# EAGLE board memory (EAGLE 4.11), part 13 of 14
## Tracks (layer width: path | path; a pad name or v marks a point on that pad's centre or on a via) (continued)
SY  (via drill 0.61) (continued)
  Bottom 0.254: 215.9,363.22 217.17,363.22 218.44,364.49 220.34,364.49 A23.S2 | 215.9,363.22 214,363.22 213.36,363.86 210.82,363.86 210.19,363.22 205.74,363.22 205.1,362.59 A24.T2 | v215.9,365.12 215.9,363.22 | v210.82,290.2 210.19,290.83 201.29,290.83 200.66,290.2 196.22,290.2 195.58,289.56 B25.U2
T0  (via drill 0.61)
  Top 0.254: v136.53,386.08 v136.53,371.48 | A33.E2 93.98,397.51 98.42,397.51 114.3,413.39 139.7,413.39 139.7,398.78 140.97,397.51 140.97,396.24 142.88,394.34 142.88,389.89 141.6,388.62 141.6,387.99 A29.J2
  Bottom 0.254: v136.53,371.48 132.08,371.48 A30.P2 | v136.53,386.08 137.16,386.72 140.97,386.72 A29.J2
T1  (via drill 0.61)
  Top 0.254: v139.7,363.22 139.7,397.51 135.25,401.96 132.08,401.96 132.08,397.51 A30.E2
  Bottom 0.254: A33.H2 93.98,391.16 94.61,391.8 99.06,391.8 102.87,395.61 107.95,395.61 108.58,396.24 111.12,396.24 112.39,394.97 120.02,394.97 121.28,396.24 123.83,396.24 125.09,394.97 128.27,394.97 129.54,396.24 131.44,396.24 A30.E2 | v139.7,363.22 137.79,363.22 137.16,363.86 130.18,363.86 128.91,362.59 A30.T2
T2  (via drill 0.61)
  Top 0.254: v95.25,377.19 95.25,382.27 93.98,383.54 A33.K2
  Route3 0.254: A30.J2 128.27,386.72 127,385.45 127,381.64 119.38,374.02 119.38,372.11 A31.P2
  Bottom 0.254: v95.25,377.19 95.89,376.56 99.06,376.56 102.87,372.75 111.76,372.75 112.39,373.38 115.57,373.38 116.84,372.11 118.75,372.11 A31.P2
T3
  Top 0.254: A31.T2 115.57,362.59 114.3,363.86 114.3,389.89 118.75,394.34 118.75,396.24 A31.E2
  Route3 0.254: A33.M2 93.98,378.46 98.42,378.46 116.2,396.24 118.75,396.24 A31.E2
T4  (via drill 0.61)
  Top 0.254: v56.52,59.05 63.5,66.04 63.5,91.44 69.85,97.79 69.85,207.01 | 69.85,207.01 69.85,305.44 73.03,308.61 v73.03,349.89 | v319.4,223.52 317.5,221.61 v317.5,214 | v71.75,207.01 69.85,207.01
  Route3 0.254: v73.03,349.89 76.2,353.06 76.2,358.14 88.9,370.84 93.34,370.84 A33.P2 | v149.86,211.45 147.96,209.55 v147.96,207.01 | A31.J2 115.57,386.72 114.3,385.45 114.3,381.64 106.68,374.02 106.68,372.11 A32.P2
  Bottom 0.254: v56.52,59.05 53.98,59.05 52.7,57.79 F36.D2 | A32.P2 106.05,372.11 101.6,372.11 100.33,373.38 97.79,373.38 96.52,372.11 93.98,372.11 A33.P2 | v319.4,223.52 325.75,223.52 327.66,225.42 331.47,225.42 C14.T2 | v317.5,214 213.36,214 212.09,215.26 173.35,215.26 172.72,214.63 153.03,214.63 v149.86,211.45 | v147.96,207.01 102.23,207.01 101.6,206.38 72.39,206.38 v71.75,207.01
T5  (via drill 0.61)
  Top 0.254: v180.97,355.6 180.97,366.4 179.71,367.67 A26.R2 | 111.12,351.16 106.68,351.16 106.68,356.24 103.5,359.41 103.5,361.31 A32.T2 | v119.38,351.16 111.12,351.16 | 111.12,351.16 111.12,382.91 104.78,389.25 104.78,394.97 106.05,396.24 A32.E2
  Route2 0.254: v140.34,352.43 139.06,351.16 v119.38,351.16
  Bottom 0.254: A33.S2 93.98,364.49 94.61,363.86 99.06,363.86 100.33,362.59 102.87,362.59 A32.T2 | v180.97,355.6 180.97,352.43 166.37,352.43 165.74,351.79 140.97,351.79 v140.34,352.43
T6  (via drill 0.61)
  Top 0.254: v96.52,358.78 98.42,360.68 98.42,373.38 100.97,375.92 100.97,376.56 101.6,377.19 101.6,385.45 102.87,386.72 A32.J2 | v334.01,212.72 334.01,220.98 334.64,221.61 C14.U2 | v212.72,213.36 212.72,285.12 215.9,288.29 215.9,323.22 212.72,326.39 212.72,375.29 v211.46,376.56 | v176.53,393.7 177.8,392.43 v177.8,378.46
  Route2 0.254: v96.52,358.78 93.98,358.78 A33.U2
  Route3 0.254: A29.L2 141.6,381.64 144.15,381.64 161.29,398.78 169.54,398.78 169.54,397.51 A27.E2
  Bottom 0.254: A29.L2 140.97,380.37 140.34,379.73 135.89,379.73 135.25,379.1 126.36,379.1 125.73,379.73 123.19,379.73 122.56,379.1 113.67,379.1 113.03,379.73 110.49,379.73 109.86,379.1 102.87,379.1 101.6,380.37 101.6,386.72 102.87,386.72 A32.J2 | v334.01,212.72 317.5,212.72 316.87,213.36 v212.72,213.36 | v211.46,376.56 210.82,377.19 208.28,377.19 A24.M2 207.65,378.46 205.74,378.46 204.47,379.73 201.29,379.73 197.49,375.92 188.59,375.92 187.32,377.19 182.88,377.19 A26.M2 182.25,378.46 v177.8,378.46 | v176.53,393.7 174.62,395.61 170.81,395.61 170.18,396.24 A27.E2
TAD  (via drill 0.61)
  Top 0.254: v254,67.31 254,52.7 255.27,51.44 F20.F2 | v254,177.16 254,233.68 255.27,234.95 v255.27,236.22 | v254,275.59 v254,250.19 | v438.15,414.02 438.15,386.08 436.88,384.81 A06.K2 | v330.2,414.66 330.2,363.86 v328.3,361.95
  Route3 0.254: v254,67.31 257.18,67.31 257.18,113.66 260.35,116.84 260.35,148.59 254,154.94 v254,177.16 | v255.27,236.22 254,237.49 v254,250.19 | v305.44,274.32 307.98,276.86 307.98,307.34 306.7,308.61 306.7,309.25 311.15,313.69 311.15,337.82 323.21,349.89 323.21,357.5 322.58,358.14 A15.U2
  Bottom 0.254: v254,275.59 255.27,276.86 269.88,276.86 271.14,275.59 302.89,275.59 304.17,274.32 v305.44,274.32 | v438.15,414.02 400.05,414.02 399.42,414.66 366.39,414.66 365.76,414.02 365.12,414.66 v330.2,414.66 | v328.3,361.95 326.39,363.86 323.85,363.86 320.68,360.68 318.13,360.68 317.5,361.31 316.23,361.31 314.32,359.41 314.32,356.87 320.68,356.87 321.94,358.14 A15.U2
TAD+IAC+CMA  (via drill 0.61)
  Top 0.254: v205.1,294 205.1,297.81 B24.R2 | v387.99,71.75 389.25,73.02 389.25,80.64 390.52,81.91 390.52,89.53 389.25,90.8 v388.62,90.8
  Route2 0.254: v205.1,294 206.38,292.74 206.38,289.56 v204.47,289.56 | v179.71,103.5 192.41,90.8 200.66,90.8 204.47,86.99 210.82,86.99 214,83.82 220.34,83.82 224.16,80.01 243.84,80.01 244.47,80.64 249.56,80.64 252.73,77.47 271.14,77.47 283.21,65.41 289.56,65.41 292.74,62.23 296.55,62.23 304.17,69.85 341,69.85 341.63,69.22 385.44,69.22 v387.99,71.75
  Route3 0.254: v204.47,289.56 193.68,278.77 193.68,224.16 187.32,217.81 187.32,178.44 184.15,175.26 184.15,172.72 v185.42,171.45 | v179.07,163.83 177.8,162.56 177.8,154.94 179.07,153.67 179.07,151.13 177.8,149.86 177.8,105.41 v179.71,103.5
  Bottom 0.254: E10.T2 382.9,89.53 384.81,91.44 385.44,91.44 E10.S2 386.08,91.44 387.99,91.44 v388.62,90.8 | v185.42,171.45 187.32,169.54 187.32,163.83 v179.07,163.83
VCC  (via drill 0.61)
  Top 0.635: v150.5,71.12 149.22,72.39 149.22,133.99 147.96,135.25 147.96,142.24 145.41,142.24 144.78,141.6 144.78,137.16 E29.A2 | 172.72,358.78 174.62,360.68 174.62,398.78 182.25,406.4 182.25,408.94 A26.A2 | 172.72,358.78 169.54,355.6 169.54,340.36 B27.A2 | 174.62,273.69 v174.62,205.1 | 174.62,273.69 176.53,275.59 182.25,275.59 182.25,273.69 C26.A2 | 172.72,358.78 174.62,356.87 174.62,273.69 | v111.12,199.39 v111.12,140.34
  Bottom 0.635: E36.A2 55.88,137.16 57.15,138.43 63.5,138.43 64.77,137.16 67.94,137.16 E35.A2 68.58,137.16 69.85,138.43 79.38,138.43 | 79.38,138.43 80.64,137.16 E34.A2 | 79.38,138.43 92.08,138.43 93.34,137.16 E33.A2 93.98,137.16 97.16,140.34 v111.12,140.34 140.97,140.34 144.15,137.16 E29.A2 144.78,137.16 146.05,138.43 155.57,138.43 156.84,137.16 E28.A2 157.48,135.89 160.02,135.89 161.29,134.62 163.83,134.62 164.47,135.25 168.91,135.25 169.54,135.89 E27.A2 170.18,135.89 172.72,135.89 173.99,134.62 176.53,134.62 177.16,135.25 181.61,135.25 182.25,135.89 E26.A2 182.88,135.89 185.42,135.89 186.69,134.62 189.23,134.62 189.87,135.25 194.31,135.25 194.94,135.89 E25.A2 195.58,135.89 198.12,135.89 199.39,134.62 201.93,134.62 202.56,135.25 207.01,135.25 207.65,135.89 E24.A2 208.28,135.89 210.82,135.89 212.09,134.62 214.63,134.62 215.26,135.25 219.71,135.25 220.34,135.89 E23.A2 220.98,135.89 221.62,135.25 226.06,135.25 226.69,134.62 227.97,134.62 229.87,136.53 233.04,136.53 E22.A2 233.68,135.89 234.31,135.25 238.76,135.25 239.4,134.62 241.3,134.62 242.57,135.89 245.75,135.89 E21.A2 246.38,135.89 247.01,135.25 251.46,135.25 252.09,134.62 254,134.62 255.27,135.89 258.44,135.89 E20.A2 259.08,135.89 259.71,135.25 264.16,135.25 264.8,134.62 266.7,134.62 267.97,135.89 271.14,135.89 E19.A2 271.78,135.89 274.32,135.89 275.59,134.62 278.13,134.62 280.04,136.53 283.85,136.53 E18.A2 284.48,135.89 285.12,135.25 289.56,135.25 290.19,134.62 292.1,134.62 293.37,135.89 296.55,135.89 E17.A2 297.18,135.89 299.72,135.89 300.99,134.62 303.53,134.62 305.44,136.53 309.25,136.53 E16.A2 309.88,136.53 313.69,136.53 315.6,134.62 316.23,134.62 316.87,135.25 321.31,135.25 321.94,135.89 E15.A2 322.58,137.16 323.21,137.79 327.66,137.79 328.3,138.43 331.47,138.43 333.38,136.53 334.64,136.53 E14.A2 335.28,135.89 337.82,135.89 339.09,134.62 341.63,134.62 342.26,135.25 346.71,135.25 347.35,135.89 E13.A2 347.98,135.89 350.52,135.89 351.79,134.62 354.33,134.62 354.96,135.25 359.41,135.25 360.05,135.89 E12.A2 360.68,136.53 363.86,136.53 365.76,134.62 367.03,134.62 368.94,136.53 372.75,136.53 E11.A2 373.38,136.53 377.19,136.53 379.1,134.62 379.73,134.62 381.63,136.53 385.44,136.53 E10.A2 386.08,135.89 390.52,135.89 391.8,134.62 393.7,134.62 394.97,135.89 398.14,135.89 E09.A2 398.78,136.53 402.59,136.53 404.5,134.62 406.4,134.62 407.67,135.89 410.85,135.89 E08.A2 411.48,135.89 412.12,135.25 416.56,135.25 417.19,134.62 419.1,134.62 420.37,135.89 423.55,135.89 E07.A2 424.18,135.89 426.72,135.89 427.99,134.62 430.53,134.62 431.17,135.25 435.61,135.25 436.25,135.89 E06.A2 436.88,135.89 439.42,135.89 440.69,134.62 443.23,134.62 443.87,135.25 448.31,135.25 448.94,135.89 E05.A2 449.58,135.89 452.12,135.89 453.39,134.62 455.93,134.62 456.56,135.25 461.01,135.25 461.64,135.89 E04.A2 462.28,135.89 464.82,135.89 466.09,134.62 468.63,134.62 470.54,136.53 474.35,136.53 E03.A2
  Bottom 0.635: F03.A2 474.35,66.04 473.71,65.41 469.26,65.41 468.63,64.77 466.09,64.77 464.82,66.04 462.28,66.04 F04.A2 461.64,67.31 460.38,68.58 450.85,68.58 449.58,67.31 F05.A2 448.94,67.31 447.68,68.58 440.69,68.58 439.42,67.31 436.88,67.31 F06.A2 436.25,67.31 434.98,68.58 422.27,68.58 | 412.75,68.58 411.48,67.31 F08.A2 | 412.75,68.58 422.27,68.58 | 422.27,68.58 423.55,67.31 F07.A2 | 412.75,68.58 404.5,68.58 402.59,66.67 398.78,66.67 F09.A2 398.14,66.04 394.97,66.04 393.7,64.77 391.8,64.77 391.16,65.41 386.71,65.41 386.08,66.04 F10.A2 385.44,66.67 381.63,66.67 379.73,64.77 377.19,64.77 375.92,66.04 373.38,66.04 F11.A2 372.75,67.31 368.3,67.31 367.03,68.58 358.77,68.58 | 15.88,68.58 6.35,68.58 5.08,67.31 F40.A2 | 15.88,68.58 17.14,67.31 F39.A2 | 28.57,68.58 29.84,67.31 F38.A2 | 28.57,68.58 15.88,68.58 | 41.27,68.58 42.55,67.31 F37.A2 | 41.27,68.58 28.57,68.58 | 53.98,68.58 55.24,67.31 F36.A2 | 53.98,68.58 41.27,68.58 | 66.67,68.58 67.94,67.31 F35.A2 | 66.67,68.58 53.98,68.58 | 79.38,68.58 80.64,67.31 F34.A2 | 79.38,68.58 66.67,68.58 | 89.53,67.94 88.27,67.94 87.63,68.58 79.38,68.58 | 89.53,67.94 92.71,67.94 93.34,67.31 F33.A2 | 168.28,68.58 158.75,68.58 157.48,67.31 F28.A2 156.84,67.31 153.67,70.48 150.5,70.48 | 168.28,68.58 169.54,67.31 F27.A2 | 168.28,68.58 180.97,68.58 182.25,67.31 F26.A2 182.88,66.04 185.42,66.04 186.69,64.77 189.23,64.77 189.87,65.41 194.31,65.41 194.94,66.04 F25.A2 195.58,66.04 198.12,66.04 199.39,64.77 201.93,64.77 202.56,65.41 207.01,65.41 207.65,66.04 F24.A2 208.28,66.67 212.09,66.67 214,64.77 214.63,64.77 215.26,65.41 219.71,65.41 220.34,66.04 F23.A2 220.98,66.04 221.62,65.41 226.06,65.41 226.69,64.77 227.33,64.77 229.24,66.67 233.04,66.67 F22.A2 233.68,66.04 234.31,65.41 238.76,65.41 239.4,64.77 241.3,64.77 242.57,66.04 245.75,66.04 F21.A2 246.38,66.04 248.92,66.04 250.19,64.77 252.73,64.77 253.37,65.41 257.81,65.41 258.44,66.04 F20.A2 259.08,66.04 261.62,66.04 262.89,64.77 265.43,64.77 266.06,65.41 270.51,65.41 271.14,66.04 F19.A2 271.78,67.31 273.05,68.58 282.57,68.58 283.85,67.31 F18.A2 284.48,66.04 287.02,66.04 288.29,64.77 290.83,64.77 292.74,66.67 296.55,66.67 F17.A2 297.18,67.31 297.81,67.94 302.26,67.94 302.89,68.58 307.98,68.58
  Bottom 0.635: 346.07,68.58 336.55,68.58 335.28,67.31 F14.A2 334.64,66.67 330.83,66.67 328.93,64.77 326.39,64.77 325.12,66.04 322.58,66.04 F15.A2 321.94,67.31 317.5,67.31 316.23,68.58 307.98,68.58 | 346.07,68.58 347.35,67.31 F13.A2 | 358.77,68.58 360.05,67.31 F12.A2 | 346.07,68.58 358.77,68.58 | 307.98,68.58 309.25,67.31 F16.A2 | 89.53,67.94 89.53,70.48 150.5,70.48 | v150.5,71.12 150.5,70.48 | B03.A2 474.35,339.09 473.71,338.46 469.26,338.46 468.63,337.82 466.09,337.82 464.82,339.09 462.28,339.09 B04.A2 461.64,339.09 461.01,338.46 456.56,338.46 455.93,337.82 453.39,337.82 452.12,339.09 449.58,339.09 B05.A2 448.94,339.09 448.31,338.46 443.87,338.46 443.23,337.82 440.69,337.82 439.42,339.09 436.88,339.09 B06.A2 436.25,339.09 433.07,339.09 431.8,337.82 429.89,337.82 429.26,338.46 424.81,338.46 424.18,339.09 B07.A2 423.55,339.09 420.37,339.09 419.1,337.82 417.19,337.82 415.29,339.73 411.48,339.73 B08.A2 410.85,339.73 408.31,339.73 406.4,337.82 404.5,337.82 403.86,338.46 399.42,338.46 398.78,339.09 B09.A2 398.14,339.09 397.51,338.46 393.06,338.46 392.43,337.82 389.89,337.82 389.25,338.46 384.81,338.46 | 384.81,338.46 385.44,339.09 B10.A2 | 384.81,338.46 380.37,338.46 379.73,337.82 377.19,337.82 375.92,339.09 373.38,339.09 B11.A2 372.75,339.09 372.11,338.46 367.67,338.46 367.03,337.82 364.49,337.82 363.22,339.09 360.68,339.09 B12.A2 360.05,339.09 359.41,338.46 354.96,338.46 354.33,337.82 351.79,337.82 350.52,339.09 347.98,339.09 B13.A2 347.35,339.09 346.71,338.46 342.26,338.46 341.63,337.82 339.09,337.82 337.82,339.09 335.28,339.09 B14.A2 334.64,339.09 334.01,338.46 329.56,338.46 328.93,337.82 326.39,337.82 325.12,339.09 322.58,339.09 B15.A2 321.94,339.09 321.31,338.46 316.87,338.46 316.23,337.82 313.69,337.82 312.42,339.09 309.88,339.09 B16.A2 309.25,339.09 306.07,339.09 304.8,337.82 302.89,337.82 302.26,338.46 297.81,338.46 297.18,339.09 B17.A2 296.55,339.09 295.91,338.46 291.46,338.46 290.83,337.82 289.56,337.82 287.65,339.73 284.48,339.73 B18.A2 283.85,339.09 283.21,338.46 278.76,338.46 278.13,337.82 275.59,337.82 274.32,339.09 271.78,339.09 B19.A2 271.14,339.09 267.97,339.09 266.7,337.82 264.8,337.82 264.16,338.46 259.71,338.46 259.08,339.09 B20.A2 258.44,339.73 255.27,339.73 253.37,337.82 252.09,337.82 251.46,338.46 247.01,338.46 246.38,339.09 B21.A2 245.75,339.09 242.57,339.09 241.3,337.82 239.4,337.82 238.76,338.46 234.31,338.46 233.68,339.09 B22.A2 233.04,339.09 229.87,339.09 228.6,337.82 226.69,337.82 226.06,338.46 221.62,338.46 220.98,339.09 B23.A2 220.34,339.09 219.71,338.46 215.26,338.46 214.63,337.82 212.09,337.82 210.82,339.09 208.28,339.09 B24.A2 207.65,339.09 207.01,338.46 202.56,338.46 201.93,337.82 199.39,337.82 198.12,339.09 195.58,339.09 B25.A2 194.94,339.09 194.31,338.46 189.87,338.46 189.23,337.82 186.69,337.82 185.42,339.09 182.88,339.09 B26.A2 182.25,339.09 179.07,339.09 177.8,337.82 175.9,337.82 175.26,338.46 170.81,338.46 170.18,339.09 B27.A2 169.54,339.73 165.74,339.73 163.83,337.82 161.29,337.82 160.02,339.09 157.48,339.09 B28.A2 156.84,339.73 153.03,339.73 151.13,337.82 148.59,337.82 147.32,339.09 144.78,339.09 B29.A2 144.15,340.36 139.7,340.36 138.43,341.63 130.18,341.63
  Bottom 0.635: 28.57,341.63 6.35,341.63 5.08,340.36 B40.A2 | 28.57,341.63 29.84,340.36 B38.A2 | 41.27,341.63 42.55,340.36 B37.A2 | 41.27,341.63 28.57,341.63 | 53.98,341.63 55.24,340.36 B36.A2 | 53.98,341.63 41.27,341.63 | 53.98,341.63 66.67,341.63 67.94,340.36 B35.A2 68.58,340.36 69.85,341.63 76.83,341.63 78.11,340.36 80.64,340.36 B34.A2 81.28,340.36 82.55,341.63 92.08,341.63 | 92.08,341.63 93.34,340.36 B33.A2 | 104.78,341.63 106.05,340.36 B32.A2 | 104.78,341.63 92.08,341.63 | 117.47,341.63 118.75,340.36 B31.A2 | 117.47,341.63 104.78,341.63 | 130.18,341.63 131.44,340.36 B30.A2 | 130.18,341.63 117.47,341.63 | 422.27,411.48 412.75,411.48 411.48,410.21 A08.A2 410.85,408.94 410.21,408.31 405.76,408.31 405.13,407.67 402.59,407.67 401.32,408.94 398.78,408.94 A09.A2 398.14,410.21 396.88,411.48 384.18,411.48 | 422.27,411.48 423.55,410.21 A07.A2 | 422.27,411.48 434.98,411.48 436.25,410.21 A06.A2 436.88,408.94 439.42,408.94 440.69,407.67 443.23,407.67 443.87,408.31 448.31,408.31 448.94,408.94 A05.A2 449.58,408.94 452.12,408.94 453.39,407.67 455.93,407.67 456.56,408.31 461.01,408.31 461.64,408.94 A04.A2 462.28,408.94 464.82,408.94 466.09,407.67 468.63,407.67 469.26,408.31 473.71,408.31 474.35,408.94 A03.A2 | 384.18,411.48 379.1,411.48 378.46,410.85 374.01,410.85 373.38,410.21 A11.A2 372.75,408.94 372.11,408.31 367.67,408.31 367.03,407.67 364.49,407.67 363.22,408.94 360.68,408.94 A12.A2 360.05,410.21 358.77,411.48 346.07,411.48 | 384.18,411.48 385.44,410.21 A10.A2 | 346.07,411.48 336.55,411.48 335.28,410.21 A14.A2 334.64,408.94 330.2,408.94 328.93,407.67 326.39,407.67 325.12,408.94 322.58,408.94 A15.A2 321.94,410.21 318.13,410.21 316.87,411.48 311.15,411.48
  Bottom 0.635: 346.07,411.48 347.35,410.21 A13.A2 | 311.15,411.48 309.88,410.21 A16.A2 | 311.15,411.48 302.89,411.48 300.99,409.58 297.18,409.58 A17.A2 296.55,408.94 293.37,408.94 292.1,407.67 290.19,407.67 289.56,408.31 285.12,408.31 284.48,408.94 A18.A2 283.85,409.58 280.04,409.58 278.13,407.67 275.59,407.67 274.32,408.94 271.78,408.94 A19.A2 271.14,408.94 270.51,408.31 266.06,408.31 265.43,407.67 262.89,407.67 261.62,408.94 259.08,408.94 A20.A2 258.44,408.94 257.81,408.31 253.37,408.31 252.73,407.67 250.19,407.67 248.92,408.94 246.38,408.94 A21.A2 245.75,408.94 245.11,408.31 240.66,408.31 240.03,407.67 237.49,407.67 236.22,408.94 233.68,408.94 A22.A2 233.04,408.94 232.41,408.31 227.97,408.31 227.33,407.67 224.79,407.67 223.52,408.94 220.98,408.94 A23.A2 220.34,408.94 219.71,408.31 215.26,408.31 214.63,407.67 212.09,407.67 210.82,408.94 208.28,408.94 A24.A2 207.65,408.94 207.01,408.31 202.56,408.31 201.93,407.67 199.39,407.67 198.12,408.94 195.58,408.94 A25.A2 194.94,408.94 194.31,408.31 189.87,408.31 189.23,407.67 186.69,407.67 185.42,408.94 182.88,408.94 A26.A2 182.25,410.21 180.97,411.48 171.45,411.48 170.18,410.21 A27.A2 169.54,410.21 165.74,410.21 164.47,411.48 158.75,411.48 157.48,410.21 A28.A2 156.84,408.94 153.67,408.94 152.4,407.67 150.5,407.67 149.86,408.31 145.41,408.31 144.78,408.94 A29.A2 144.15,408.94 140.97,408.94 139.7,407.67 137.79,407.67 137.16,408.31 132.72,408.31 132.08,408.94 A30.A2 131.44,410.21 130.18,411.48 117.47,411.48 | 15.88,411.48 6.35,411.48 5.08,410.21 A40.A2 | 15.88,411.48 17.14,410.21 A39.A2
  Bottom 0.635: 28.57,411.48 29.84,410.21 A38.A2 | 28.57,411.48 15.88,411.48 | 41.27,411.48 42.55,410.21 A37.A2 | 41.27,411.48 28.57,411.48 | 53.98,411.48 55.24,410.21 A36.A2 | 53.98,411.48 41.27,411.48 | 66.67,411.48 67.94,410.21 A35.A2 | 66.67,411.48 53.98,411.48 | 79.38,411.48 80.64,410.21 A34.A2 | 79.38,411.48 66.67,411.48 | 92.08,411.48 93.34,410.21 A33.A2 | 92.08,411.48 79.38,411.48 | 104.78,411.48 106.05,410.21 A32.A2 | 104.78,411.48 92.08,411.48 | 117.47,411.48 118.75,410.21 A31.A2 | 117.47,411.48 104.78,411.48 | 28.57,205.1 19.05,205.1 17.78,203.84 D39.A2 | 28.57,205.1 29.84,203.84 D38.A2 | 28.57,205.1 41.27,205.1 42.55,203.84 D37.A2 43.18,202.56 45.72,202.56 46.99,201.29 49.53,201.29 50.16,201.93 54.61,201.93 55.24,202.56 D36.A2 55.88,202.56 58.42,202.56 59.69,201.29 62.23,201.29 62.87,201.93 67.31,201.93 67.94,202.56 D35.A2 68.58,202.56 71.12,202.56 72.39,201.29 74.93,201.29 75.56,201.93 80.01,201.93 80.64,202.56 D34.A2 81.28,203.2 85.09,203.2 87,201.29 88.9,201.29 90.17,202.56 93.34,202.56 D33.A2 93.98,202.56 94.61,201.93 99.06,201.93 99.69,201.29 101.6,201.29 102.87,202.56 106.05,202.56 D32.A2 106.68,202.56 109.22,202.56 110.49,201.29 111.12,201.29 | 111.12,201.29 113.03,201.29 113.67,201.93 118.11,201.93 118.75,202.56 D31.A2 119.38,202.56 121.92,202.56 123.19,201.29 125.73,201.29 126.36,201.93 130.81,201.93 131.44,202.56 D30.A2 132.08,202.56 134.62,202.56 135.89,201.29 138.43,201.29 139.06,201.93 143.51,201.93 144.15,202.56 D29.A2 144.78,202.56 145.41,201.93 149.86,201.93 150.5,201.29 152.4,201.29 153.67,202.56 156.84,202.56 D28.A2 157.48,203.84 161.93,203.84 163.19,205.1 168.28,205.1
  Bottom 0.635: 168.28,205.1 169.54,203.84 D27.A2 | 168.28,205.1 v174.62,205.1 180.97,205.1 182.25,203.84 D26.A2 182.88,202.56 185.42,202.56 186.69,201.29 189.23,201.29 190.5,202.56 194.94,202.56 D25.A2 195.58,203.84 196.85,205.1 206.38,205.1 207.65,203.84 D24.A2 208.28,202.56 208.91,201.93 213.36,201.93 214,201.29 215.9,201.29 217.81,203.2 220.34,203.2 D23.A2 220.98,203.84 222.25,205.1 231.78,205.1 | D03.A2 474.35,202.56 473.71,201.93 469.26,201.93 468.63,201.29 466.09,201.29 464.82,202.56 462.28,202.56 D04.A2 461.64,202.56 461.01,201.93 456.56,201.93 455.93,201.29 453.39,201.29 452.12,202.56 449.58,202.56 D05.A2 448.94,202.56 445.77,202.56 444.5,201.29 442.6,201.29 441.96,201.93 437.51,201.93 436.88,202.56 D06.A2 436.25,202.56 433.07,202.56 431.8,201.29 429.89,201.29 429.26,201.93 424.81,201.93 424.18,202.56 D07.A2 423.55,202.56 422.91,201.93 418.46,201.93 417.83,201.29 415.29,201.29 414.02,202.56 411.48,202.56 D08.A2 410.85,202.56 407.67,202.56 406.4,201.29 404.5,201.29 403.86,201.93 399.42,201.93 398.78,202.56 D09.A2 398.14,203.2 394.33,203.2 392.43,201.29 391.16,201.29 389.25,203.2 386.08,203.2 D10.A2 385.44,202.56 384.81,201.93 380.37,201.93 379.73,201.29 377.19,201.29 375.92,202.56 373.38,202.56 D11.A2 372.75,202.56 369.57,202.56 368.3,201.29 366.39,201.29 365.76,201.93 361.31,201.93 360.68,202.56 D12.A2 360.05,203.2 356.24,203.2 354.33,201.29 351.79,201.29 350.52,202.56 347.98,202.56 D13.A2 347.35,202.56 346.71,201.93 342.26,201.93 341.63,201.29 339.09,201.29 337.82,202.56 335.28,202.56 D14.A2 334.64,202.56 334.01,201.93 329.56,201.93 328.93,201.29 326.39,201.29 325.12,202.56 322.58,202.56 D15.A2 321.94,202.56 321.31,201.93 316.87,201.93 316.23,201.29 313.69,201.29 312.42,202.56 309.88,202.56 D16.A2 309.25,202.56 308.61,201.93 304.17,201.93 303.53,201.29 300.99,201.29 299.72,202.56 297.18,202.56 D17.A2 296.55,202.56 293.37,202.56 292.1,201.29 290.19,201.29 289.56,201.93 285.12,201.93 284.48,202.56 D18.A2 283.85,202.56 280.67,202.56 279.4,201.29 277.5,201.29 276.86,201.93 272.42,201.93 271.78,202.56 D19.A2 271.14,203.84 269.88,205.1 257.18,205.1
  Bottom 0.635: 231.78,205.1 233.04,203.84 D22.A2 | 244.47,205.1 245.75,203.84 D21.A2 | 231.78,205.1 244.47,205.1 | 257.18,205.1 258.44,203.84 D20.A2 | 244.47,205.1 257.18,205.1 | C03.A2 474.35,273.05 471.17,273.05 469.26,271.15 468,271.15 467.36,271.78 462.92,271.78 462.28,272.42 C04.A2 461.64,272.42 461.01,271.78 456.56,271.78 455.93,271.15 453.39,271.15 452.75,271.78 448.31,271.78 | 448.31,271.78 448.94,272.42 C05.A2 | 448.31,271.78 443.87,271.78 443.23,271.15 440.69,271.15 439.42,272.42 436.88,272.42 C06.A2 436.25,272.42 435.61,271.78 431.17,271.78 430.53,271.15 427.99,271.15 426.72,272.42 424.18,272.42 C07.A2 423.55,272.42 420.37,272.42 419.1,271.15 417.19,271.15 416.56,271.78 412.12,271.78 411.48,272.42 C08.A2 410.85,273.05 407.04,273.05 405.13,271.15 403.86,271.15 401.95,273.05 398.78,273.05 C09.A2 398.14,272.42 397.51,271.78 393.06,271.78 392.43,271.15 389.89,271.15 388.62,272.42 386.08,272.42 C10.A2 385.44,273.05 381.63,273.05 379.73,274.96 371.48,274.96 | 371.48,274.96 366.39,274.96 364.49,273.05 360.68,273.05 C12.A2 360.05,272.42 359.41,271.78 354.96,271.78 354.33,271.15 353.06,271.15 351.15,273.05 347.98,273.05 C13.A2 347.35,273.05 343.54,273.05 341.63,271.15 339.09,271.15 337.82,272.42 335.28,272.42 C14.A2 334.64,272.42 334.01,271.78 329.56,271.78 328.93,271.15 326.39,271.15 325.12,272.42 322.58,272.42 C15.A2 321.94,272.42 321.31,271.78 316.87,271.78 316.23,271.15 313.69,271.15 312.42,272.42 309.88,272.42 C16.A2 309.25,272.42 308.61,271.78 304.17,271.78 303.53,271.15 300.99,271.15 299.72,272.42 297.18,272.42 C17.A2 296.55,272.42 293.37,272.42 292.1,271.15 290.19,271.15 288.93,272.42 284.48,272.42 C18.A2 283.85,272.42 283.21,271.78 278.76,271.78 278.13,271.15 276.86,271.15 274.95,273.05 271.78,273.05 C19.A2 271.14,272.42 267.97,272.42 266.7,271.15 264.8,271.15 264.16,271.78 259.71,271.78 259.08,272.42 C20.A2 258.44,273.05 254.63,273.05 252.73,271.15 250.19,271.15 248.92,272.42 246.38,272.42 C21.A2 245.75,272.42 245.11,271.78 240.66,271.78 240.03,271.15 238.76,271.15 236.85,273.05 233.68,273.05 C22.A2 233.04,273.69 228.6,273.69 227.33,274.96 219.07,274.96
  Bottom 0.635: 371.48,274.96 372.75,273.69 C11.A2 | 219.07,274.96 209.55,274.96 208.28,273.69 C24.A2 207.65,273.05 203.84,273.05 201.93,271.15 199.39,271.15 198.12,272.42 195.58,272.42 C25.A2 194.94,272.42 194.31,271.78 189.87,271.78 189.23,271.15 186.69,271.15 185.42,272.42 182.88,272.42 C26.A2 182.25,273.05 178.44,273.05 176.53,274.96 168.28,274.96 | 219.07,274.96 220.34,273.69 C23.A2 | C40.A2 5.08,272.42 5.71,271.78 10.16,271.78 10.79,271.15 12.7,271.15 13.97,272.42 17.14,272.42 C39.A2 17.78,272.42 20.32,272.42 21.59,271.15 24.13,271.15 24.77,271.78 29.21,271.78 29.84,272.42 C38.A2 30.48,272.42 33.02,272.42 34.29,271.15 36.83,271.15 37.47,271.78 41.91,271.78 42.55,272.42 C37.A2 43.18,272.42 45.72,272.42 46.99,271.15 49.53,271.15 50.16,271.78 54.61,271.78 55.24,272.42 C36.A2 55.88,272.42 56.52,271.78 60.96,271.78 61.59,271.15 63.5,271.15 64.77,272.42 67.94,272.42 C35.A2 68.58,272.42 69.22,271.78 73.66,271.78 74.3,271.15 76.2,271.15 77.47,272.42 80.64,272.42 C34.A2 81.28,272.42 83.82,272.42 85.09,271.15 87.63,271.15 88.27,271.78 92.71,271.78 93.34,272.42 C33.A2 93.98,273.05 97.16,273.05 99.06,274.96 104.78,274.96 106.05,273.69 C32.A2 106.68,272.42 109.22,272.42 110.49,271.15 113.03,271.15 113.67,271.78 118.11,271.78 118.75,272.42 C31.A2 119.38,273.69 123.83,273.69 125.09,274.96 130.18,274.96 131.44,273.69 C30.A2 132.08,272.42 134.62,272.42 135.89,271.15 138.43,271.15 139.06,271.78 143.51,271.78 144.15,272.42 C29.A2 144.78,272.42 147.32,272.42 148.59,271.15 151.13,271.15 151.76,271.78 156.21,271.78 156.84,272.42 C28.A2 157.48,273.69 158.75,274.96 168.28,274.96
  Bottom 0.635: 168.28,274.96 169.54,273.69 C27.A2 | 111.12,201.29 v111.12,199.39
WR\  (via drill 0.61)
  Top 0.254: v160.66,177.16 160.02,177.8 160.02,179.07 158.75,180.34 158.75,216.53 157.48,217.81 157.48,221.61 C28.U2
  Bottom 0.254: v160.66,177.16 161.93,175.89 165.74,175.89 166.37,175.26 D27.L2
WR_RQ  (via drill 0.61)
  Top 0.254: 104.78,141.6 104.78,160.02 103.5,161.29 D32.R2 | 104.78,141.6 104.78,20.95 103.5,19.69 F32.T2 | v142.88,140.97 142.88,125.73 144.15,124.46 E29.E2 | v103.5,141.6 104.78,141.6
  Bottom 0.254: v142.88,140.97 140.97,142.88 120.02,142.88 118.75,141.6 v103.5,141.6
WRITE  (via drill 0.61)
  Top 0.254: v128.91,185.42 127,183.51 127,65.41 v125.09,63.5 | v116.2,61.59 116.2,57.79 F31.D2
  Bottom 0.254: F32.E2 106.68,54.61 107.31,55.25 111.76,55.25 113.03,56.52 115.57,56.52 F31.D2 | v128.91,185.42 135.25,185.42 135.89,186.06 140.34,186.06 140.97,186.69 D29.F2 | v125.09,63.5 123.19,61.59 v116.2,61.59
WT_INCR  (via drill 0.61)
  Top 0.254: v189.23,298.45 187.32,300.36 v187.32,346.08 | v325.12,340.36 325.75,341 325.75,353.7 327.02,354.97 v327.02,387.35 | v334.64,387.35 334.64,389.89 A14.H2
  Route2 0.254: v189.23,298.45 191.77,298.45 B25.R2 | v334.64,387.35 332.11,387.35 A14.J2
  Bottom 0.254: v187.32,346.08 215.9,346.08 216.53,346.71 222.88,346.71 224.16,345.44 241.94,345.44 242.57,346.08 247.65,346.08 250.19,343.54 264.8,343.54 265.43,344.17 297.18,344.17 298.45,345.44 300.36,345.44 303.53,342.27 316.23,342.27 318.13,340.36 320.68,340.36 321.31,341 324.49,341 v325.12,340.36 | v327.02,387.35 331.47,387.35 A14.J2
WTB  (via drill 0.61)
  Top 0.254: v385.44,167 384.18,168.28 v384.18,208.28 | v346.71,208.28 342.9,212.09 342.9,233.04 344.17,234.31 344.17,237.49 C13.N2 | v442.6,354.97 444.5,356.87 444.5,375.29 448.31,379.1 448.31,382.91 448.94,383.54 A05.K2 | v429.89,219.07 429.26,218.44 429.26,208.28 v429.89,207.64
  Route2 0.254: v401.32,157.48 400.05,158.75 400.05,163.83 397.51,163.83 391.16,170.18 388.62,170.18 v385.44,167
  Route3 0.254: v414.65,377.83 411.48,374.65 411.48,374.02 412.75,372.75 412.75,363.86 407.67,363.86 403.23,359.41 398.78,359.41 A09.U2 | v430.53,349.89 428.62,347.98 428.62,273.69 427.36,272.42 427.36,271.78 428.62,270.51 428.62,220.34 v429.89,219.07
  Bottom 0.254: v414.65,377.83 422.27,385.45 429.26,385.45 433.07,389.25 441.96,389.25 446.4,384.81 448.94,384.81 A05.K2 | v401.32,157.48 403.23,157.48 403.23,155.57 404.5,154.31 409.57,154.31 410.85,153.03 D08.U2 | v346.71,208.28 347.98,209.55 366.39,209.55 367.03,208.91 383.54,208.91 v384.18,208.28 385.44,207.01 390.52,207.01 391.8,208.28 429.26,208.28 v429.89,207.64 | v442.6,354.97 440.69,353.06 433.7,353.06 v430.53,349.89
WTB*A00(B)  (via drill 0.61)
  Top 0.254: v117.47,131.44 117.47,153.67 116.2,154.94 D31.T2
  Route2 0.254: v117.47,131.44 117.47,124.46 118.75,124.46 E31.E2
WTD  (via drill 0.61)
  Top 0.254: v447.68,374.02 447.68,367.03 448.94,365.76 A05.S2 | v337.82,117.47 339.73,119.38 339.73,231.14 342.9,234.31 342.9,259.08 344.17,260.35 344.17,262.89 C13.D2 344.17,264.16 344.17,266.7 342.9,267.97 v342.9,274.96 | v304.8,316.23 v304.8,276.23 | v309.88,399.42 307.98,397.51 v307.98,364.49 | v313.06,358.78 313.69,358.14 313.69,356.87 314.96,355.6 314.96,341 314.32,340.36 v314.32,326.39
  Route2 0.254: A08.M2 410.85,378.46 410.85,380.37 401.95,389.25 399.42,389.25 398.78,389.89 A09.H2 398.14,391.16 396.88,392.43 389.89,392.43 389.25,391.8 380.37,391.8 373.38,398.78 364.49,398.78 363.86,398.15 354.96,398.15 351.15,401.96 v343.54,401.96 | v337.82,117.47 335.28,117.47 E14.H2
  Route3 0.254: v307.98,364.49 313.06,359.41 v313.06,358.78 | v314.32,326.39 314.32,322.58 v312.42,320.68
  Bottom 0.254: v447.68,374.02 447.68,375.92 440.69,375.92 440.06,376.56 431.17,376.56 430.53,375.92 427.99,375.92 427.36,376.56 421.64,376.56 421,375.92 415.29,375.92 414.02,377.19 411.48,377.19 A08.M2 | v304.8,276.23 306.07,274.96 325.12,274.96 325.75,274.32 327.66,274.32 328.93,275.59 342.26,275.59 v342.9,274.96 | B17.J2 294,316.87 294.64,316.23 299.08,316.23 299.72,315.6 302.26,315.6 302.89,316.23 v304.8,316.23 304.8,320.04 306.7,321.95 311.15,321.95 v312.42,320.68 | v343.54,401.96 342.9,401.32 339.09,401.32 338.45,401.96 329.56,401.96 328.93,401.32 326.39,401.32 325.75,401.96 316.87,401.96 316.23,401.32 313.69,401.32 313.06,401.96 312.42,401.96 v309.88,399.42
WTD(B)  (via drill 0.61)
  Top 0.254: v111.12,73.66 111.12,139.06 113.03,140.97 v113.03,148.59
  Route2 0.254: v111.12,73.66 111.12,33.66 117.47,27.3 118.75,27.3 118.75,22.86 F31.S2 | v113.03,148.59 128.27,163.83 137.16,163.83 138.43,162.56 140.97,162.56 D29.R2
WTE  (via drill 0.61)
  Top 0.254: A10.U2 385.44,359.41 384.18,360.68 384.18,366.4 382.9,367.67 A10.R2 | 395.61,338.46 391.8,342.27 v391.8,354.97 | 403.23,330.84 395.61,338.46 | 403.23,330.84 v403.86,330.2 | v419.74,164.47 419.1,165.1 v419.1,276.23 | v404.5,279.4 403.23,280.67 403.23,330.84 | v450.85,342.9 450.85,375.92 449.58,377.19 A05.M2 | v399.42,342.9 395.61,339.09 395.61,338.46 | v179.07,278.13 180.97,280.04 180.97,290.2 179.71,291.47 B26.T2 | v76.2,277.5 76.2,379.1 77.47,380.37 A34.L2 | v319.4,300.99 317.5,299.09 v317.5,279.4 | v187.96,284.48 185.42,281.94 v185.42,278.13
  Route2 0.254: v419.74,164.47 423.55,164.47 D07.P2 | v319.4,300.99 321.94,300.99 B15.P2 | v404.5,279.4 404.5,276.23 392.43,276.23 391.16,274.96 363.86,274.96 363.22,274.32 362.58,274.32 v361.95,274.96
  Route3 0.254: v253.37,280.67 v253.37,284.48 | v332.11,274.32 331.47,274.96 v331.47,279.4
  Bottom 0.254: A15.R2 319.4,367.67 320.68,366.4 327.66,366.4 330.83,369.57 337.19,369.57 337.82,370.21 340.36,370.21 344.17,366.4 351.79,366.4 355.6,370.21 365.76,370.21 366.39,369.57 375.29,369.57 375.92,370.21 377.82,370.21 379.73,368.3 382.27,368.3 A10.R2 | v403.86,330.2 407.67,330.2 B08.D2 | v391.8,354.97 388.62,358.14 386.08,358.14 A10.U2 | v419.1,276.23 415.93,279.4 v404.5,279.4 | v450.85,342.9 450.21,342.27 400.69,342.27 400.05,342.9 v399.42,342.9 | v76.2,277.5 76.83,278.13 139.06,278.13 140.34,276.86 161.93,276.86 163.83,278.77 178.44,278.77 v179.07,278.13 v185.42,278.13 | v253.37,280.67 254,280.04 291.46,280.04 292.1,280.67 292.74,280.04 316.87,280.04 v317.5,279.4 v331.47,279.4 | v253.37,284.48 250.19,284.48 249.56,283.85 188.59,283.85 v187.96,284.48 | v361.95,274.96 361.31,274.32 354.96,274.32 354.33,274.96 344.17,274.96 342.9,273.69 341.63,274.96 332.74,274.96 v332.11,274.32
WTE*-[(ISZ*ZI)+JMS+(OP+IOT)*SKP+JMP]  (via drill 0.61)
  Top 0.254: E14.M2 335.28,105.41 335.28,109.22 336.55,110.49 336.55,217.17 335.28,218.44 335.28,220.34 336.55,221.61 336.55,236.22 335.28,237.49 335.28,240.66 C14.M2
  Route2 0.254: v389.25,254 384.81,249.56 377.19,249.56 374.01,246.38 367.67,246.38 367.03,245.75 364.49,245.75 361.31,248.92 358.77,248.92 v354.33,244.47
  Route3 0.254: v391.8,276.86 390.52,275.59 390.52,255.27 v389.25,254
  Bottom 0.254: v391.8,276.86 399.42,276.86 399.42,280.04 396.24,283.21 395.61,283.21 395.61,283.85 402.59,290.83 407.04,290.83 407.67,291.47 B08.T2 | v354.33,244.47 352.43,242.57 342.26,242.57 341.63,243.2 339.73,243.2 337.82,241.3 335.28,241.3 C14.M2
WTE*[(ISZ*ZI)+JMS+(OP+IOT)*SKP]  (via drill 0.61)
  Top 0.254: E14.R2 332.11,95.88 333.38,97.16 333.38,137.16 332.74,137.79 332.74,147.95 333.38,148.59 333.38,212.09 332.74,212.72 332.74,217.81 333.38,218.44 333.38,246.38 332.11,247.65 332.11,250.19 C14.J2 | v288.93,354.97 v288.93,368.3 | v302.89,356.24 304.17,354.97 304.17,346.71 307.98,342.9 v307.98,308.61
  Route2 0.254: v288.93,368.3 288.93,367.67 287.65,366.4 282.57,366.4 281.31,367.67 A18.R2 | v288.93,354.97 290.19,353.7 297.18,353.7 298.45,352.43 299.08,352.43 v302.89,356.24
  Route3 0.254: v307.98,308.61 308.61,309.25 314.32,309.25 314.32,293.37 v315.6,292.1 | v320.68,288.93 320.68,287.66 330.2,278.13 330.2,267.34 333.38,264.16 333.38,252.73 332.11,251.46 C14.J2
  Bottom 0.254: v315.6,292.1 318.77,288.93 v320.68,288.93
WTF  (via drill 0.61)
  Top 0.254: v393.7,240.66 393.7,233.68 394.97,232.41 C09.R2 | v347.35,108.58 349.25,110.49 v349.25,142.24 | D08.M2 411.48,170.81 412.75,169.54 412.75,151.76 410.21,149.22 410.21,141.6 v403.23,141.6 403.23,89.53 v405.13,87.63 | v406.4,229.23 406.4,217.17 v404.5,215.26 | v315.6,304.17 318.77,307.34 318.77,310.52 B15.L2 319.4,311.79 319.4,314.96 320.68,316.23 320.68,363.22 | 320.68,363.22 320.68,381.64 320.04,382.27 320.04,386.08 319.4,386.72 A15.J2 | v321.94,363.22 320.68,363.22 | v403.23,392.43 403.23,367.03 400.05,363.86 | 400.05,363.86 v398.14,361.95 | B36.M2 55.24,308.61 53.98,309.88 53.98,315.6 52.7,316.87 B36.J2 | v180.97,349.25 180.97,323.22 180.34,322.58 180.34,318.77 179.71,318.14 B26.J2 | 225.43,354.97 v225.43,348.62 | 225.43,354.97 229.87,359.41 229.87,361.31 A22.T2 | v223.52,389.25 225.43,389.25 225.43,354.97 | v391.8,280.04 393.7,281.94 v393.7,298.45 | v394.97,300.99 396.88,302.9 v396.88,317.5 | v393.7,343.54 400.05,349.89 400.05,363.86
  Route2 0.254: 400.69,247.65 403.86,250.82 407.67,250.82 C08.J2 | 400.69,247.65 v393.7,240.66 | 400.69,247.65 396.24,252.09 394.33,252.09 388.62,246.38 384.18,246.38 382.9,245.11 C10.L2 | v347.35,108.58 344.81,108.58 E13.L2 | 400.69,247.65 406.4,241.94 406.4,231.14 407.04,230.5 407.04,229.23 v406.4,229.23 | v396.88,193.67 396.88,185.42 403.86,185.42 404.5,186.06 410.21,186.06 v410.85,186.69 | v321.94,363.22 322.58,363.86 325.75,363.86 326.39,363.22 328.93,363.22 332.11,366.4 338.45,366.4 339.09,367.03 347.98,367.03 351.79,363.22 360.68,363.22 364.49,367.03 368.94,367.03 369.57,367.67 A11.R2 370.2,367.67 371.48,366.4 376.56,366.4 377.19,367.03 386.08,367.03 389.89,363.22 396.88,363.22 v398.14,361.95
  Route3 0.254: v424.18,81.91 424.18,69.85 422.27,67.94 422.27,53.34 431.8,43.82 431.8,40.01 433.07,38.73 F06.L2 | v401.95,214 400.69,212.72 400.69,201.29 396.88,197.48 v396.88,193.67 | v410.85,186.69 409.57,185.42 409.57,174.62 411.48,172.72 411.48,172.09 D08.M2 | v306.7,389.89 300.36,396.24 v300.36,396.88 | v384.18,278.77 385.44,277.5 385.44,276.23 384.18,274.96 384.18,272.42 384.81,271.78 384.81,267.97 384.18,267.34 384.18,246.38 382.9,245.11 C10.L2 | v393.7,298.45 393.7,299.72 v394.97,300.99 | v396.88,317.5 396.88,325.12 393.7,328.3 v393.7,343.54
  Bottom 0.254: C12.K2 360.68,247.01 361.31,246.38 365.76,246.38 366.39,245.75 375.29,245.75 375.92,246.38 377.82,246.38 379.73,244.47 382.27,244.47 C10.L2 | v349.25,142.24 349.88,141.6 375.92,141.6 376.56,140.97 399.42,140.97 400.05,141.6 v403.23,141.6 | v424.18,81.91 423.55,81.28 417.83,81.28 411.48,87.63 v405.13,87.63 | v404.5,215.26 403.23,214 v401.95,214 | A06.E2 436.25,397.51 434.98,398.78 429.89,398.78 429.26,398.15 421.64,398.15 415.29,391.8 412.12,391.8 411.48,391.16 A08.H2 410.85,391.16 409.57,392.43 v403.23,392.43 | v315.6,304.17 314.32,302.9 312.42,302.9 311.79,303.53 302.89,303.53 302.26,302.9 297.81,302.9 297.18,302.26 B17.P2 | v180.97,349.25 209.55,349.25 210.19,348.62 v225.43,348.62 | 215.26,393.7 219.71,389.25 v223.52,389.25 | 215.26,393.7 210.19,398.78 201.29,398.78 199.39,396.88 195.58,396.88 A25.E2 | B36.J2 52.7,318.14 53.98,319.41 60.96,319.41 61.59,318.77 70.48,318.77 71.12,319.41 73.66,319.41 74.3,318.77 83.19,318.77 83.82,319.41 86.36,319.41 87,318.77 95.89,318.77 99.69,322.58 100.97,322.58 104.14,319.41 111.76,319.41 112.39,318.77 113.67,318.77 114.3,319.41 124.46,319.41 125.09,318.77 133.99,318.77 134.62,319.41 137.16,319.41 137.79,318.77 146.69,318.77 147.32,319.41 149.86,319.41 150.5,318.77 159.38,318.77 160.02,319.41 162.56,319.41 163.19,318.77 172.09,318.77 172.72,319.41 173.35,319.41 174.62,318.14 179.07,318.14 B26.J2 | v306.7,389.89 307.34,389.25 313.06,389.25 314.32,387.99 318.77,387.99 A15.J2 | v300.36,396.88 296.55,400.69 295.27,400.69 294.64,401.32 288.29,401.32 287.65,401.96 278.76,401.96 274.95,398.15 266.06,398.15 265.43,398.78 262.89,398.78 262.25,398.15 253.37,398.15 252.73,398.78 250.19,398.78 249.56,398.15 240.66,398.15 240.03,398.78 237.49,398.78 236.85,398.15 227.97,398.15 227.33,398.78 224.79,398.78 224.16,398.15 219.71,398.15 215.26,393.7
  Bottom 0.254: v384.18,278.77 384.81,278.13 389.89,278.13 v391.8,280.04
WTF(B)  (via drill 0.61)
  Top 0.254: v150.5,20.32 152.4,20.32 152.4,132.72 149.22,135.89 v149.22,148.59 | v141.6,151.13 141.6,154.94 D29.T2
  Bottom 0.254: v150.5,20.32 149.86,20.95 147.32,20.95 146.69,20.32 137.79,20.32 137.16,20.95 134.62,20.95 133.99,20.32 125.09,20.32 124.46,20.95 117.47,20.95 116.2,19.69 F31.T2 | v149.22,148.59 149.22,151.13 v141.6,151.13
WTF*-(OP+IOT)  (via drill 0.61)
  Top 0.254: B17.T2 294,292.74 294,296.55 295.27,297.81 295.27,302.26 296.55,303.53 296.55,307.34 B17.M2 | B08.L2 408.31,311.79 408.94,312.42 408.94,316.23 409.57,316.87 409.57,337.19 408.31,338.46 408.31,353.7 409.57,354.97 409.57,398.15 408.31,399.42 A08.D2
  Route2 0.254: v306.07,313.69 303.53,316.23 300.99,316.23 297.81,313.06 297.18,313.06 297.18,308.61 B17.M2 | v367.03,312.42 370.2,315.6 378.46,315.6 379.1,316.23 387.99,316.23 394.97,309.25 403.86,309.25 405.13,310.52 407.67,310.52 B08.L2
  Bottom 0.254: v306.07,313.69 307.98,315.6 314.96,315.6 315.6,316.23 321.31,316.23 321.94,315.6 327.66,315.6 328.3,316.23 337.19,316.23 341,312.42 349.88,312.42 350.52,313.06 353.06,313.06 353.69,312.42 362.58,312.42 363.22,313.06 365.76,313.06 366.39,312.42 v367.03,312.42
WTF*BT(00-06)  (via drill 0.61)
  Top 0.254: v229.87,137.79 229.24,138.43 v229.24,142.24
  Route2 0.254: v321.94,126.36 320.04,128.27 313.69,128.27 309.88,132.08 300.99,132.08 300.36,131.44 291.46,131.44 283.85,139.06 263.52,139.06 252.73,128.27 250.19,128.27 249.56,128.91 243.21,128.91 234.31,137.79 v229.87,137.79 | v229.24,142.24 224.16,147.32 221.62,147.32 v201.29,167.64 | v208.28,225.42 v201.93,219.07 | v224.16,278.77 225.43,280.04 226.06,280.04 226.69,279.4 234.31,279.4 v236.22,281.31 | v281.31,377.83 282.57,379.1 288.29,379.1 292.1,382.91 302.26,382.91 302.89,382.27 311.79,382.27 312.42,382.91 314.96,382.91 315.6,382.27 324.49,382.27 325.12,382.91 327.66,382.91 328.3,382.27 337.19,382.27 341,386.08 349.88,386.08 353.69,382.27 362.58,382.27 363.22,382.91 365.76,382.91 366.39,382.27 375.29,382.27 375.92,382.91 378.46,382.91 382.27,379.1 391.16,379.1 392.43,380.37 394.97,380.37 A09.L2
  Route3 0.254: v201.29,167.64 200.03,168.91 200.03,208.91 202.56,211.45 202.56,218.44 v201.93,219.07 | v208.28,225.42 209.55,226.69 209.55,258.44 219.07,267.97 219.07,273.69 v224.16,278.77 | v236.22,281.31 238.12,283.21 238.12,309.25 244.47,315.6 244.47,321.95 247.65,325.12 247.65,346.71 254,353.06 254,358.14 257.18,361.31 257.18,365.76 264.8,373.38 273.69,373.38 274.32,372.75 276.86,372.75 276.86,373.38 v281.31,377.83
  Bottom 0.254: v321.94,126.36 323.21,126.36 324.49,125.09 325.75,125.09 326.39,125.73 333.38,125.73 334.64,124.46 E14.E2
WTF*BT(07-11)*-PGZ  (via drill 0.61)
  Route2 0.254: v338.45,98.42 340.36,100.33 349.88,100.33 350.52,99.69 351.79,99.69 358.14,106.04 365.76,106.04 372.11,112.39 378.46,112.39 v379.1,113.03
  Route3 0.254: v338.45,98.42 336.55,96.52 336.55,87.63 335.28,86.36 E14.U2 | v379.1,113.03 381,114.93 381,140.97 378.46,143.51 378.46,151.13 377.82,151.76 377.82,186.69 381,189.86 381,205.1 379.73,206.38 379.73,220.34 381,221.61 381,227.97 384.18,231.14 384.18,241.94 v385.44,243.2
  Bottom 0.254: v385.44,243.2 385.44,246.38 384.81,246.38 384.18,247.01 384.18,248.92 391.16,248.92 392.43,250.19 394.97,250.19 C09.J2
WTF+WTB+EX+DC+LD  (via drill 0.61)
  Top 0.254: v339.73,234.95 v339.73,285.12
  Route3 0.254: v339.73,234.95 335.28,234.95 C14.P2
  Bottom 0.254: v339.73,285.12 344.17,285.12 B13.V2 344.81,286.39 345.44,286.39 347.35,288.29 B13.U2
WTF+WTI+WTD+WTB  (via drill 0.61)
  Top 0.254: B16.U2 309.88,289.56 310.51,290.2 310.51,294 311.15,294.64 311.15,309.88 309.88,311.15 309.88,313.69 B16.K2 309.88,314.96 311.15,316.23 311.15,337.19 311.79,337.82 311.79,342.27 v313.69,344.17 | v336.55,344.17 v336.55,365.12
  Route2 0.254: A14.P2 334.64,372.11 332.74,374.02 332.11,374.02 A14.N2
  Route3 0.254: v336.55,365.12 336.55,365.76 335.92,366.4 335.92,370.21 335.28,370.84 A14.P2
  Bottom 0.254: v313.69,344.17 v336.55,344.17
WTI  (via drill 0.61)
  Top 0.254: v412.75,344.17 412.75,326.39 412.12,325.75 412.12,321.95 411.48,321.31 B08.H2 411.48,320.04 412.12,319.41 412.12,315.6 412.75,314.96 412.75,254.63 v414.02,253.36 | v449.58,344.81 449.58,358.14 A05.U2 | v422.27,246.38 424.18,244.47 424.18,243.84 422.27,241.94 422.27,192.41 423.55,191.13 D07.E2
  Route2 0.254: v422.27,246.38 419.1,249.56 415.29,249.56 414.65,248.92 413.38,248.92 411.48,250.82 | 411.48,250.82 408.94,253.36 407.67,253.36 401.95,259.08 400.69,259.08 399.42,257.81 395.61,257.81 C09.F2 | v414.02,253.36 411.48,250.82
  Bottom 0.254: v412.75,344.17 413.38,344.81 v449.58,344.81
WTI+(WTX*TAD)+(WTX*ISZ)  (via drill 0.61)
  Top 0.254: v168.28,346.71 168.28,366.4 167,367.67 A27.R2 | v299.72,344.17 301.62,342.27 v301.62,278.13 | v381,277.5 381,252.73 382.27,251.46 C10.J2
  Bottom 0.254: v168.28,346.71 170.18,344.81 215.9,344.81 217.17,346.08 222.25,346.08 223.52,344.81 242.57,344.81 243.21,345.44 247.01,345.44 249.56,342.9 265.43,342.9 266.06,343.54 297.81,343.54 298.45,344.17 v299.72,344.17 | v301.62,278.13 316.23,278.13 316.87,277.5 350.52,277.5 352.43,279.4 353.69,278.13 366.39,278.13 367.03,277.5 v381,277.5 | C10.H2 385.44,253.36 383.54,251.46 382.9,251.46 C10.J2
WTINC_PC  (via drill 0.61)
  Top 0.254: v179.07,384.18 184.15,379.1 v184.15,347.35 | v327.02,346.08 v327.02,275.59 | v360.05,275.59 361.95,273.69 361.95,257.81 360.68,256.54 360.68,254.63 C12.H2
  Bottom 0.254: v179.07,384.18 177.16,386.08 175.9,386.08 175.26,385.45 172.72,385.45 172.09,386.08 167.64,386.08 167,386.72 A27.J2 | v184.15,347.35 207.65,347.35 208.28,346.71 215.26,346.71 215.9,347.35 223.52,347.35 224.79,346.08 241.3,346.08 241.94,346.71 248.28,346.71 250.82,344.17 264.16,344.17 264.8,344.81 296.55,344.81 297.81,346.08 v327.02,346.08 | v327.02,275.59 327.66,276.23 359.41,276.23 v360.05,275.59 | C12.J2 357.5,251.46 359.41,253.36 360.05,253.36 C12.H2
WTS  (via drill 0.61)
  Top 0.254: v400.05,184.15 v400.05,168.91 | v404.5,198.75 405.76,200.03 405.76,201.93 407.67,203.84 407.67,218.44 C08.V2 | v90.81,420.37 57.78,420.37 38.1,400.69 38.1,389.25 39.37,387.99 A37.J2 | v417.83,420.37 424.18,420.37 424.81,421 447.04,421 447.04,407.67 447.68,407.04 447.68,392.43 448.94,391.16 A05.H2
  Route2 0.254: v363.22,135.25 370.2,142.24 375.29,142.24 376.56,143.51 v382.27,143.51 | v90.81,420.37 92.08,421.64 169.54,421.64 171.45,419.74 179.07,419.74 180.97,421.64 309.25,421.64 311.15,419.74 414.02,419.74 415.93,421.64 416.56,421.64 v417.83,420.37
  Route3 0.254: v363.22,135.25 361.95,133.99 361.95,108.58 358.77,105.41 358.77,100.96 358.14,100.33 358.14,98.42 355.6,95.88 355.6,94.61 356.24,93.98 356.24,90.17 356.87,89.53 E12.T2 | v394.97,143.51 397.51,146.05 397.51,149.22 400.05,151.76 v400.05,168.91 | v400.05,184.15 400.05,194.31 v404.5,198.75 | v408.31,221.61 408.31,219.71 C08.V2 | v414.65,222.25 415.93,223.52 415.93,236.85 417.19,238.12 417.19,239.39 415.93,240.66 415.93,249.56 422.91,256.54 422.91,257.18 v424.18,258.44 | v442.6,263.53 444.5,265.43 444.5,299.72 447.68,302.9 447.68,316.87 450.85,320.04 450.85,341.63 452.12,342.9 452.12,353.7 450.85,354.97 450.85,388.62 449.58,389.89 A05.H2
  Bottom 0.254: v394.97,143.51 v382.27,143.51 | v408.31,221.61 408.94,220.98 412.75,220.98 414.02,222.25 v414.65,222.25 | v424.18,258.44 427.99,262.25 438.79,262.25 439.42,261.62 440.69,261.62 v442.6,263.53
WTX  (via drill 0.61)
  Top 0.254: v285.75,1.27 v285.75,5.71 285.75,29.21 285.12,29.84 285.12,33.66 284.48,34.29 F18.M2 | v200.03,1.27 193.68,7.62 193.68,20.32 194.94,21.59 F25.S2 | v295.27,358.14 295.27,332.11 294,330.84 B17.D2 294,329.56 294,327.66 v295.91,325.75 | 244.47,360.68 244.47,366.4 243.21,367.67 A21.R2 | 244.47,360.68 244.47,332.11 243.21,330.84 B21.D2 | v194.94,360.68 194.94,364.49 A25.S2 194.94,365.76 194.94,368.94 193.68,370.21 193.68,379.1 192.41,380.37 A25.L2 | v203.2,360.68 203.2,313.06 204.47,311.79 B24.L2 | v243.84,360.68 244.47,360.68 | 387.35,376.56 384.81,376.56 384.18,377.19 384.18,379.1 382.9,380.37 A10.L2 | 387.35,378.46 387.35,388.62 | 387.35,376.56 387.35,378.46 | 387.35,388.62 386.08,389.89 A10.H2 | 387.35,388.62 387.35,399.42 382.9,399.42 A10.D2 | 387.35,378.46 v392.43,373.38 | v353.06,248.92 352.43,248.28 v352.43,232.41 | 387.35,376.56 387.35,285.75 386.08,284.48 386.08,274.96 387.35,273.69 v387.35,233.04 387.35,220.34 386.08,219.07 386.08,205.1 387.35,203.84 v387.35,171.45 387.35,87.63 386.08,86.36 E10.U2 386.08,85.09 386.08,72.39 390.52,67.94 390.52,43.18 384.18,36.83 384.18,20.95 v383.54,20.32 | v337.82,4.44 338.45,3.81 338.45,3.17 339.73,1.9 374.01,1.9 374.01,14.61 374.65,15.24 v374.65,20.95
  Route2 0.254: D06.H2 436.25,183.51 434.98,182.25 431.17,182.25 424.18,175.26 421,175.26 D07.L2
  Route3 0.254: B15.U2 321.94,289.56 321.31,290.2 321.31,294 320.68,294.64 320.68,318.77 321.94,320.04 B15.H2 321.94,321.31 v321.94,325.12 | v319.4,377.83 316.23,374.65 316.23,374.02 317.5,372.75 317.5,363.86 318.77,362.59 A15.T2
  Bottom 0.254: F40.S2 5.08,22.86 5.71,23.49 10.16,23.49 10.79,24.13 19.68,24.13 20.32,23.49 22.86,23.49 23.5,24.13 32.38,24.13 33.02,23.49 35.56,23.49 36.2,24.13 45.09,24.13 48.9,20.32 57.78,20.32 61.59,24.13 70.48,24.13 74.3,20.32 83.19,20.32 90.17,27.3 99.06,27.3 102.87,23.49 111.76,23.49 115.57,27.3 124.46,27.3 125.09,26.67 133.99,26.67 134.62,27.3 137.16,27.3 140.97,23.49 149.86,23.49 150.5,24.13 159.38,24.13 160.02,23.49 162.56,23.49 163.19,24.13 172.09,24.13 172.72,23.49 175.26,23.49 175.9,24.13 184.78,24.13 185.42,23.49 187.96,23.49 188.59,24.13 193.68,24.13 194.94,22.86 F25.S2 | v285.75,1.27 285.12,0.63 200.66,0.63 v200.03,1.27 | 295.27,360.05 v295.27,358.14 | 295.27,360.05 302.26,360.05 302.89,360.68 311.79,360.68 312.42,360.05 313.69,360.05 315.6,361.95 318.77,361.95 A15.T2 | v321.94,325.12 313.69,325.12 313.06,325.75 304.17,325.75 303.53,325.12 300.99,325.12 300.36,325.75 v295.91,325.75 | A26.T2 179.71,361.31 180.34,360.68 184.78,360.68 185.42,360.05 187.96,360.05 188.59,360.68 v194.94,360.68 195.58,360.05 198.75,360.05 199.39,360.68 v203.2,360.68 203.84,360.05 211.46,360.05 212.09,360.68 214.63,360.68 215.26,360.05 224.16,360.05 224.79,360.68 227.33,360.68 227.97,360.05 236.85,360.05 237.49,360.68 v243.84,360.68 244.47,360.05 249.56,360.05 250.19,360.68 252.73,360.68 253.37,360.05 262.25,360.05 262.89,360.68 265.43,360.68 266.06,360.05 274.95,360.05 275.59,360.68 278.13,360.68 278.76,360.05 287.65,360.05 288.29,360.68 294.64,360.68 295.27,360.05 | v392.43,373.38 393.06,372.75 401.95,372.75 402.59,373.38 411.48,373.38 415.29,369.57 424.18,369.57 427.99,373.38 430.53,373.38 431.17,372.75 440.06,372.75 440.69,373.38 443.23,373.38 443.87,372.75 448.31,372.75 448.94,372.11 A05.P2
  Bottom 0.254: v387.35,171.45 388.62,172.72 391.16,172.72 391.8,173.35 400.69,173.35 401.32,172.72 403.86,172.72 407.67,176.53 415.29,176.53 417.19,174.62 420.37,174.62 D07.L2 | v387.35,233.04 379.1,233.04 378.46,233.68 375.92,233.68 375.29,233.04 366.39,233.04 365.76,233.68 363.22,233.68 362.58,233.04 358.14,233.04 357.5,232.41 C12.R2 356.87,231.78 353.06,231.78 v352.43,232.41 | v353.06,248.92 346.07,248.92 344.81,250.19 C13.J2 | v319.4,377.83 320.68,379.1 323.21,379.1 323.85,378.46 327.02,378.46 331.47,382.91 340.36,382.91 341,382.27 349.88,382.27 350.52,382.91 353.06,382.91 353.69,382.27 362.58,382.27 363.22,382.91 365.76,382.91 366.39,382.27 375.29,382.27 375.92,382.91 378.46,382.91 379.73,381.64 382.27,381.64 A10.L2 | v285.75,5.71 286.38,5.08 292.1,5.08 294,3.17 336.55,3.17 v337.82,4.44 | v374.65,20.95 378.46,20.95 379.1,20.32 v383.54,20.32
WTX(B)  (via drill 0.61)
  Top 0.254: v180.97,12.06 187.32,18.41 187.32,24.77 191.77,24.77 F25.R2
  Route3 0.254: v180.97,12.06 174.62,5.71 142.88,5.71 142.88,20.32 111.12,52.07 111.12,71.12 114.3,74.29 114.3,125.09 115.57,126.36 E31.D2
WTX*(JMP+JMS)  (via drill 0.61)
  Top 0.254: v379.73,369.57 377.82,367.67 v377.82,359.41
  Route2 0.254: v210.82,137.16 219.07,128.91 224.79,128.91 228.6,125.09 v229.87,125.09 | v322.58,256.54 325.12,259.08 325.75,259.08 326.39,258.44 328.93,258.44 330.2,259.72 334.64,259.72 C14.E2
  Route3 0.254: v325.75,358.78 325.75,358.14 327.02,356.87 327.02,354.97 325.75,353.7 325.75,346.08 327.02,344.81 327.02,286.39 333.38,280.04 333.38,266.06 334.01,265.43 334.01,261.62 334.64,260.99 C14.E2 | v321.94,356.87 320.68,358.14 320.68,372.75 319.4,374.02 A15.N2 | v157.48,95.25 158.75,96.52 158.75,137.16 v157.48,138.43 | v322.58,256.54 320.68,254.63 320.68,183.51 323.85,180.34 323.85,140.34 320.68,137.16 v320.68,126.36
